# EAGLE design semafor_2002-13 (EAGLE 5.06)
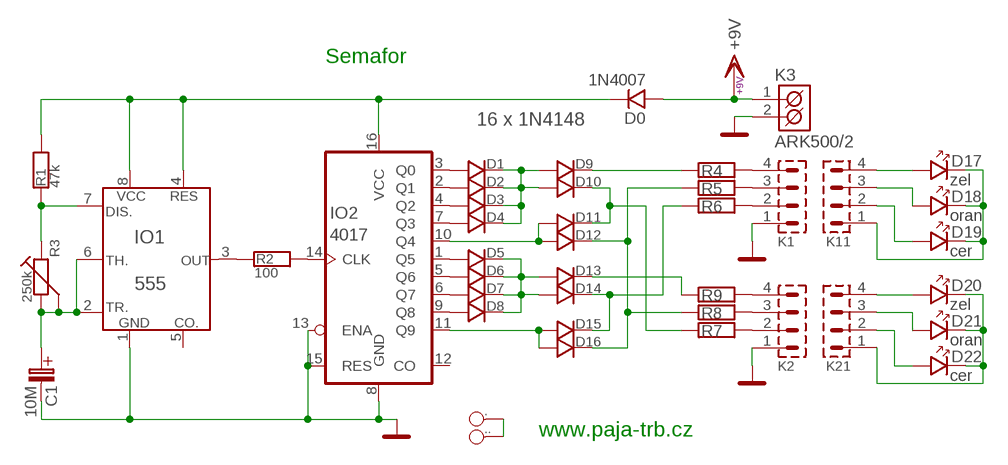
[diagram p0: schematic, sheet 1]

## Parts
.  PAD_1---  [PAD_1---]
..  PAD_1---  [PAD_1---]
C1  10M  C-ELEKTROLYT_2  [C-EL_2]
D0  1N4007  1N4007_10  [DO41]
D1  1N4148  [D 7,5]
D2  1N4148  [D 7,5]
D3  1N4148  [D 7,5]
D4  1N4148  [D 7,5]
D5  1N4148  [D 7,5]
D6  1N4148  [D 7,5]
D7  1N4148  [D 7,5]
D8  1N4148  [D 7,5]
D9  1N4148  [D 7,5]
D10  1N4148  [D 7,5]
D11  1N4148  [D 7,5]
D12  1N4148  [D 7,5]
D13  1N4148  [D 7,5]
D14  1N4148  [D 7,5]
D15  1N4148  [D 7,5]
D16  1N4148  [D 7,5]
D17  zel  LED_10  [LED_10]
D18  oran  LED_10  [LED_10]
D19  cer  LED_10  [LED_10]
D20  zel  LED_10  [LED_10]
D21  oran  LED_10  [LED_10]
D22  cer  LED_10  [LED_10]
IO1  555  [DIL8]
IO2  4017  [DIL16]
K1  PSH02-04P  [PSH02-04P]
K2  PSH02-04P  [PSH02-04P]
K3  ARK500/2  [ARK500/2]
K11  PSH02-04P  [PSH02-04P]
K21  PSH02-04P  [PSH02-04P]
R1  47k  R 7,5  [R 7,5]
R2  100  R 7,5  [R 7,5]
R3  250k  PT-10V_LEZ  [PT10V]
R4  R_STOJ  [R-STOJ]
R5  R_STOJ  [R-STOJ]
R6  R_STOJ  [R-STOJ]
R7  R_STOJ  [R-STOJ]
R8  R_STOJ  [R-STOJ]
R9  R_STOJ  [R-STOJ]

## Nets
9V: D0.K IO1.4(RES) IO1.8(VCC) IO2.16(VCC) R1.2
+9V: D0.A K3.1(K1)
GND: C1.C-(C_EL-) IO1.1(GND) IO2.8(GND) IO2.13(ENA) IO2.15(RES) K1.1 K2.1 K3.2(K2)
N$1: D1.A IO2.3(Q0)
N$2: D2.A IO2.2(Q1)
N$3: D3.A IO2.4(Q2)
N$4: D4.A IO2.7(Q3)
N$5: D5.A IO2.1(Q5)
N$6: D6.A IO2.5(Q6)
N$7: D7.A IO2.6(Q7)
N$8: D8.A IO2.9(Q8)
N$9: ..1 ...1 D5.K D6.K D7.K D8.K D13.A D14.A
N$10: D15.A D16.A IO2.11(Q9)
N$11: D11.A D12.A IO2.10(Q4)
N$12: D1.K D2.K D3.K D4.K D9.A D10.A
N$13: D10.K D11.K R7.1
N$14: D9.K R4.1
N$15: D12.K D16.K R5.1 R8.1
N$16: D14.K D15.K R6.1
N$17: D13.K R9.1
N$18: IO2.14(CLK) R2.2
N$19: IO1.3(OUT) R2.1
N$20: D17.A K11.4
N$21: C1.C+(C_EL+) IO1.2(TR.) IO1.6(TH.) R3.2 R3.3
N$22: D18.A K11.3
N$23: D19.A K11.2
N$24: IO1.7(DIS.) R1.1 R3.1
N$25: K1.4 R4.2
N$26: D17.K D18.K D19.K K11.1
N$27: D20.A K21.4
N$28: D21.A K21.3
N$29: D22.A K21.2
N$30: D20.K D21.K D22.K K21.1
N$31: K1.3 R5.2
N$32: K1.2 R6.2
N$33: K2.2 R7.2
N$34: K2.3 R8.2
N$35: K2.4 R9.2
Unconnected: IO1.5(CO.) IO2.12(CO)

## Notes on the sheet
- Semafor
- 16 x 1N4148
- www.paja-trb.cz

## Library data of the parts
. .. = #PaJa_31:PAD_1---: Pajeci bod - 2,54 mm, oval
C1 = #PaJa_31:C-ELEKTROLYT: Kondenzator - elektrolyticky
D0 = #PaJa_31:1N4007: Usmernovaci dioda - 1A, 1000V
D1-D16 = 1_PaJa_8:1N4148
D17-D22 = #PaJa_31:LED: LED - jednobarevna
IO1 = 1_PaJa_8:555
IO2 = 1_PaJa_p:4017
K1 K2 K11 K21 = #PaJa_konektory:PSH02-04: Konektory se zamkem - vidlice - 4pin
K3 = #PaJa_konektory:ARK500/2: Svorkovnice - roztec 5mm - dvojita
R1 R2 = 1_PaJa_8:R 7,5
R3 = 1_PaJa_8:PT-10V_LEZ
R4-R9 = #PaJa_31:R: Rezistor

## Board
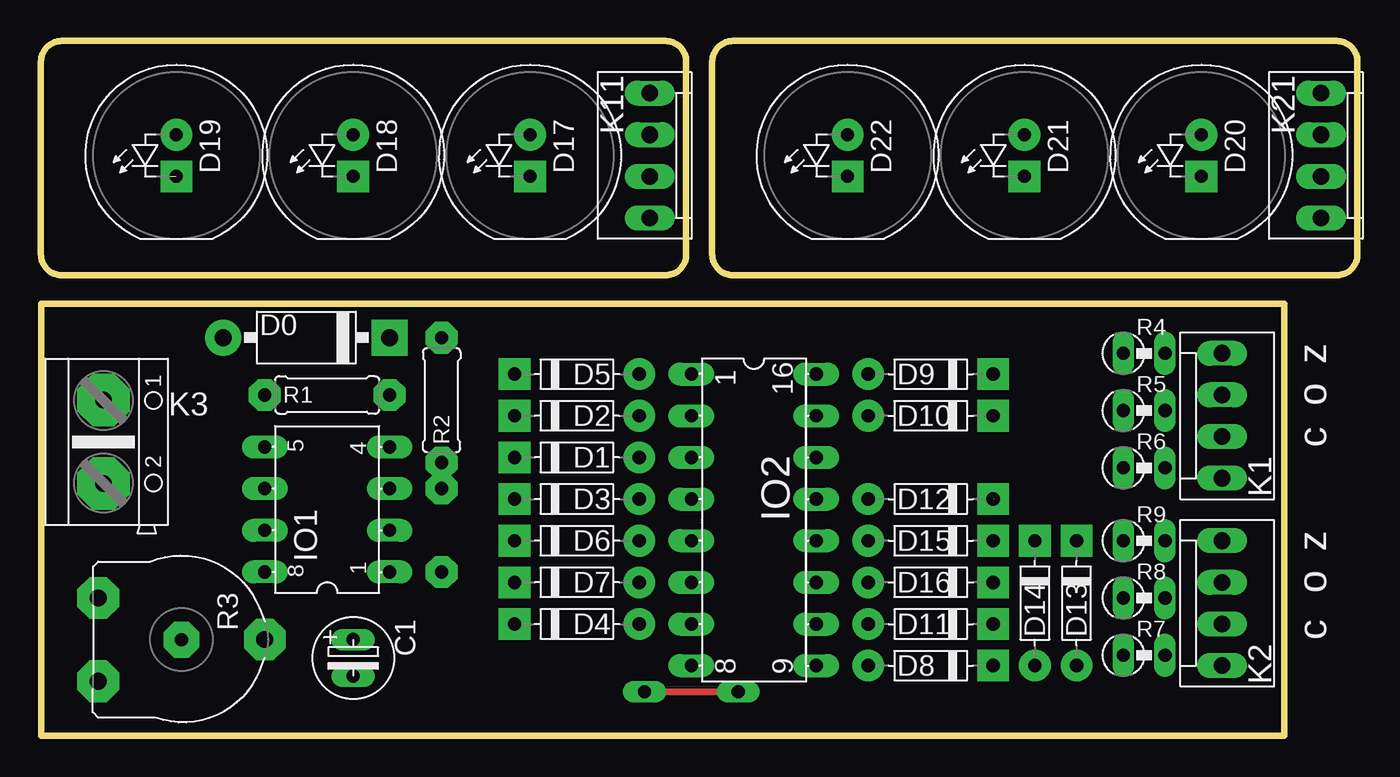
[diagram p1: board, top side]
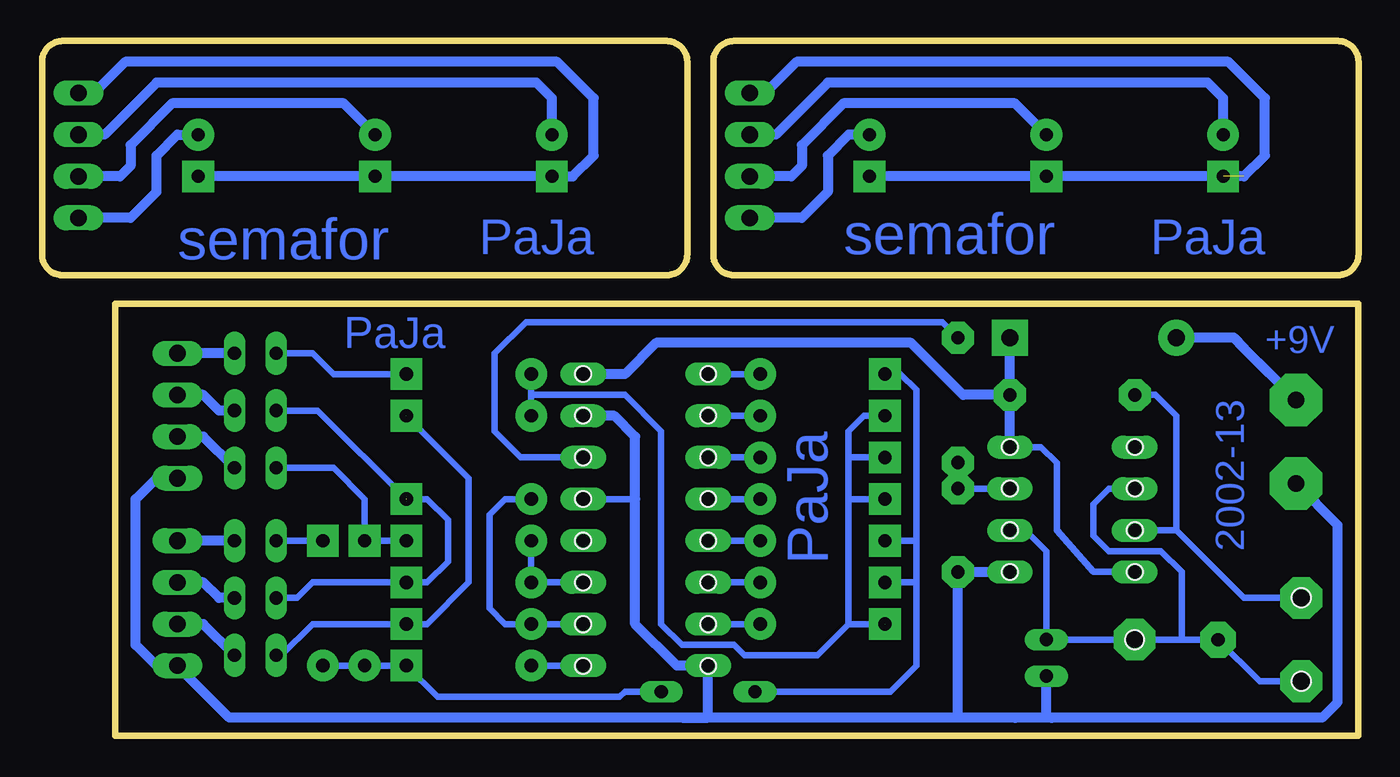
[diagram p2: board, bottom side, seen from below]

Size 80.33 x 42.38 mm. Coordinates in mm from the lower left corner, seen from the top.
Outline: 0.01,0 75.87,0 75.87,26.34 0.01,26.34 0.01,0
Outline: 39.37,29.36 39.37,41.11 arc90 38.1,42.38 1.27,42.38 arc90 0,41.11 0,29.36 arc90 1.27,28.09 38.1,28.09 arc90 39.37,29.36
Outline: 80.33,29.36 80.33,41.11 arc90 79.06,42.38 42.23,42.38 arc90 40.96,41.11 40.96,29.36 arc90 42.23,28.09 79.06,28.09 arc90 80.33,29.36
Copper layers (1*16): Top 0.035mm / dielectric 1.5mm / Bottom 0.035mm
Design rules "default": minimum track width 10mil, minimum drill 24mil, track to track 8mil, track to pad 8mil, pad to pad 8mil, via to via 8mil, smd to smd 8mil, copper to edge 40mil, drill to drill 8mil, minimum pad ring 10mil, minimum via ring 8mil, stop-mask expansion 4mil, vias tented up to drill 0mil, thermal gap 10mil

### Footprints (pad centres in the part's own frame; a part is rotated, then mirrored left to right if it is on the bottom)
PAD_1--- = drill 0.813 pad 1.27 long: 1 0,0
C-EL_2 = drill 0.813 pad 1.27 long: C+ 0,0; C- 2.223,0
DO41 = drill 1.016 pad 2.184 round: A -5.08,0 | drill 1.016 pad 2.184 square: K 5.08,0
DO35 = drill 0.813 pad 1.93 round: A -3.81,0 | drill 0.813 pad 1.93 square: K 3.81,0
LED_10 = drill 0.813 pad 1.93 round: A -1.27,0 | drill 0.813 pad 1.93 square: K 1.27,0
DIL8 = drill 0.813 pad 1.4 long: 1 -3.81,-3.81; 2 -1.27,-3.81; 3 1.27,-3.81; 4 3.81,-3.81; 5 3.81,3.81; 6 1.27,3.81; 7 -1.27,3.81; 8 -3.81,3.81
DIL16 = drill 0.813 pad 1.4 long: 1 -8.89,-3.81; 2 -6.35,-3.81; 3 -3.81,-3.81; 4 -1.27,-3.81; 5 1.27,-3.81; 6 3.81,-3.81; 7 6.35,-3.81; 8 8.89,-3.81; 9 8.89,3.81; 10 6.35,3.81; 11 3.81,3.81; 12 1.27,3.81; 13 -1.27,3.81; 14 -3.81,3.81; 15 -6.35,3.81; 16 -8.89,3.81
PSH02-04P = drill 1.016 pad 1.422 long: 1 -3.81,0; 2 -1.27,0; 3 1.27,0; 4 3.81,0
ARK500/2 = drill 1 pad 3.2 octagon: 1 -2.54,0; 2 2.54,0
R-7,5 = drill 0.813 pad 1.93 octagon: 1 -3.81,0; 2 3.81,0
PT10V = drill 1.016 pad 2.54 octagon: 1 -2.54,-5.08; 2 2.54,-5.08; 3 0,5.08
R-STOJ = drill 0.813 pad 1.27 long: 1 -1.27,0; 2 1.27,0

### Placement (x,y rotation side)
.  36.83,2.69 0 top
..  42.55,2.69 0 top
C1  19.05,5.87 270 top
D0  16.19,24.28 0 top
D1  1N4148  [DO35]  32.7,16.98 180 top
D2  1N4148  [DO35]  32.7,19.52 180 top
D3  1N4148  [DO35]  32.7,14.44 180 top
D4  1N4148  [DO35]  32.7,6.82 180 top
D5  1N4148  [DO35]  32.7,22.06 180 top
D6  1N4148  [DO35]  32.7,11.9 180 top
D7  1N4148  [DO35]  32.7,9.36 180 top
D8  1N4148  [DO35]  54.29,4.28 0 top
D9  1N4148  [DO35]  54.29,22.06 0 top
D10  1N4148  [DO35]  54.29,19.52 0 top
D11  1N4148  [DO35]  54.29,6.82 0 top
D12  1N4148  [DO35]  54.29,14.44 0 top
D13  1N4148  [DO35]  63.18,8.09 90 top
D14  1N4148  [DO35]  60.64,8.09 90 top
D15  1N4148  [DO35]  54.29,11.9 0 top
D16  1N4148  [DO35]  54.29,9.36 0 top
D17  29.84,35.4 270 top
D18  19.05,35.4 270 top
D19  8.26,35.4 270 top
D20  70.8,35.4 270 top
D21  60.01,35.4 270 top
D22  49.21,35.4 270 top
IO1  17.46,13.8 90 top
IO2  43.5,13.17 270 top
K1  72.07,19.52 90 top
K2  72.07,8.09 90 top
K3  3.81,17.93 270 top
K11  37.15,35.4 270 top
K21  78.11,35.4 270 top
R1  47k  [R-7,5]  17.46,20.79 0 top
R2  100  [R-7,5]  24.45,20.47 90 top
R3  8.57,5.87 270 top
R4  67.31,23.33 0 top
R5  67.31,19.84 0 top
R6  67.31,16.34 0 top
R7  67.31,4.92 0 top
R8  67.31,8.41 0 top
R9  67.31,11.9 0 top

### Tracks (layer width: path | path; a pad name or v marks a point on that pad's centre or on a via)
9V
  Bottom 0.406: IO1.8 16.19,9.99 18.41,12.54 18.41,16.66 19.37,17.61 IO1.4 | R1.2 | D0.K
  Bottom 0.61: IO1.4 R1.2 | R1.2 24.13,20.79 27.3,23.96 42.86,23.96 44.77,22.06 IO2.16 | R1.2 D0.K
+9V
  Bottom 0.61: D0.A 7.62,24.28 6.99,23.65 | 6.99,23.65 5.4,22.06 | K3.1 6.99,23.65
GND  (via drill 0.81 pad 1.93)
  Bottom 0.406: 44.13,14.44 IO2.13 | C1.C- 19.05,3.33 | 19.05,1.11 18.73,1.11 18.73,1.1 | 19.05,2.06 C1.C-
  Bottom 0.61: IO2.15 45.4,19.52 44.13,18.25 44.13,14.44 44.13,6.82 41.59,4.28 IO2.8 39.69,1.11 41.27,1.11 | 24.45,1.11 41.27,1.11 | 24.45,1.11 20.95,1.1 18.73,1.1 | 18.73,1.11 2.22,1.11 1.27,2.06 1.27,12.85 K3.2 | 19.05,1.11 19.05,2.06 C1.C- | IO1.1 v24.45,9.99 24.45,1.11 | K1.1 73.34,15.71 74.61,14.44 74.61,5.55 73.34,4.28 K2.1 68.9,1.11 41.27,1.11
N$1
  Bottom 0.406: D1.A IO2.3
N$2
  Bottom 0.406: D2.A IO2.2
N$3
  Bottom 0.406: D3.A IO2.4
N$4
  Bottom 0.406: D4.A IO2.7
N$5
  Bottom 0.406: D5.A IO2.1
N$6
  Bottom 0.406: D6.A IO2.5
N$7
  Bottom 0.406: D7.A IO2.6
N$8
  Bottom 0.406: IO2.9 D8.A
N$9
  Top 0.406: ..1 ...1
  Bottom 0.406: 59.05,4.28 D14.A | D14.A | D13.A D14.A | 26.99,9.36 26.99,11.9 | 26.99,11.9 26.99,21.11 27.94,22.06 D5.K | 26.99,9.36 27.62,9.36 | 27.62,9.36 D7.K | 26.99,11.9 27.62,11.9 | 26.99,9.36 26.99,4.28 28.57,2.69 ..1 | ...1 44.77,2.69 45.09,2.38 56.2,2.38 D8.K 59.05,4.28 | 59.05,4.28 D8.K | 27.62,9.36 D7.K | 27.62,11.9 D6.K | 27.62,11.9 D6.K
N$10
  Bottom 0.406: D16.A | IO2.11 D16.A | D15.A D16.A
N$11
  Bottom 0.406: D12.A 52.07,14.44 53.02,13.49 53.02,7.77 52.07,6.82 D11.A | D11.A | IO2.10 D11.A
N$12  (1 unrouted)
  Bottom 0.406: D2.K 30.16,19.52 31.11,18.57 31.11,16.98 | D1.K 31.11,16.98 | 31.11,6.82 31.11,14.44 | 50.48,20.79 44.77,20.79 42.55,18.57 42.55,6.82 41.27,5.55 38.1,5.55 37.47,4.92 33.02,4.92 31.11,6.82 | 50.48,20.79 D9.A | 50.48,20.79 D10.A | D3.K 31.11,14.44 | 31.11,14.44 31.11,16.98 | D4.K 31.11,6.82 | 50.48,20.79 D9.A
N$13  (1 unrouted)
  Bottom 0.406: D11.K 59.37,6.82 63.82,6.82 65.72,4.92 R7.1 | D11.K | D11.K 56.83,6.82 54.29,9.36 54.29,15.71 56.83,18.25 D10.K
N$14
  Bottom 0.406: D9.K 62.55,22.06 63.82,23.33 R4.1
N$15  (1 unrouted)
  Bottom 0.406: 63.82,9.36 62.23,9.36 | 63.82,9.36 D16.K 56.83,9.36 55.56,10.63 55.56,13.17 56.83,14.44 D12.K 63.5,19.84 R5.1 | 63.82,9.36 64.77,8.41 R8.1
N$16
  Bottom 0.406: D14.K | D14.K 60.64,14.44 62.55,16.34 R6.1 | D14.K D15.K
N$17
  Bottom 0.406: D13.K R9.1
N$18
  Bottom 0.406: IO2.14 51.12,16.98 52.7,18.57 52.7,23.33 50.8,25.23 25.4,25.23 R2.2
N$19  (via drill 0.81 pad 1.93)
  Bottom 0.406: IO1.3 v24.45,15.07 R2.1
N$20
  Bottom 0.61: D17.A 31.11,36.67 32.38,35.39 32.38,33.17 33.97,31.59 35.88,31.59 35.88,31.58 K11.4
N$21  (via drill 0.8 pad 2.18)
  Bottom 0.406: IO1.6 15.24,15.07 16.19,14.12 16.19,12.22 15.24,11.27 12.06,11.27 10.79,9.99 10.79,5.87 | IO1.2 20.32,12.54 19.05,11.27 C1.C+ | C1.C+ | C1.C+ R3.3 10.79,5.87 | 10.79,5.87 v8.57,5.87 6.03,3.33 R3.2
N$22
  Bottom 0.61: D18.A 20.95,38.57 31.43,38.57 33.97,36.03 33.97,34.76 34.61,34.12 K11.3
N$23
  Bottom 0.61: D19.A 8.26,38.89 9.21,39.84 32.38,39.84 35.56,36.67 K11.2
N$24
  Bottom 0.406: 12.7,20.79 12.38,20.79 11.11,19.52 11.11,12.54 | 12.7,20.79 R1.1 | 11.11,12.54 IO1.7 | 11.11,12.54 6.99,8.41 R3.1 | 12.7,20.79 R1.1
N$25
  Bottom 0.61: R4.2 K1.4
N$26  (1 unrouted)
  Bottom 0.61: D17.K D18.K 6.99,34.12 5.71,35.39 5.71,38.89 7.94,41.11 34.29,41.11 36.2,39.21 K11.1
N$27
  Bottom 0.61: D20.A 72.07,36.67 73.34,35.39 73.34,33.17 74.93,31.59 76.83,31.59 76.84,31.58 K21.4
N$28
  Bottom 0.61: D21.A 61.91,38.57 72.39,38.57 74.93,36.03 74.93,34.76 75.57,34.12 K21.3
N$29
  Bottom 0.61: D22.A 49.21,38.89 50.16,39.84 73.34,39.84 76.51,36.67 K21.2
N$30
  Bottom 0.61: K21.1 77.15,39.21 75.25,41.11 48.9,41.11 46.67,38.89 46.67,35.39 47.94,34.12 D22.K D21.K D20.K
N$31
  Bottom 0.61: K1.3 70.48,20.79 69.53,19.84 R5.2
N$32
  Bottom 0.61: K1.2 70.48,18.25 R6.2
N$33
  Bottom 0.61: R7.2 70.48,6.82 K2.2
N$34
  Bottom 0.61: K2.3 70.48,9.36 69.53,8.41 R8.2
N$35
  Bottom 0.61: R9.2 K2.4

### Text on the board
Bottom: PaJa | semafor | PaJa | semafor | +9V | PaJa | PaJa | 2002-13
tNames: z | o | c | z | o | c
tValues: +
Kola: +9V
